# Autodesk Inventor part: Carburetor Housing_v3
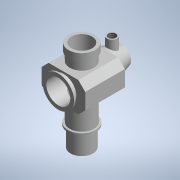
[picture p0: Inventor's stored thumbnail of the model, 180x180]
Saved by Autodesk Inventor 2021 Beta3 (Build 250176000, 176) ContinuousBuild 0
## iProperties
Created: 2012-08
Part Number: Carburetor Housing_v3
Material: Aluminum 6061
Document SubType Name: Modeling
Designer: John
Density: 2.71 g/cm^3
Mass: 9.58727 g
Surface Area: 43.1099 cm^2
Volume: 3.53774 cm^3
Appearance: Aluminum - Flat
Author: John
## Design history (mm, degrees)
sketch "Sketch1"
  geometry: L1 (-9.614, -8.788)-(9.614, -8.788); L2 (9.614, -8.788)-(9.614, 8.788); L3 (9.614, 8.788)-(-9.614, 8.788); L4 (-9.614, 8.788)-(-9.614, -8.788); L5 (-9.614, -8.788)-(9.614, 8.788); 2 further points
  constraints: 10 end point, 2 parallel, 1 coincident, 1 horizontal, 1 midpoint, 1 perpendicular
  dimensions: "d0" = 19.2278 distance of L2.end L3.end; "d2" = 17.5768 distance of L1.end L2.end
extrude "Extrusion1" new body sketch "Sketch1" stored distance "d3" = 13.1572; taper "d4" = 0 deg
sketch "Sketch2"
  geometry: L1 (9.614, 8.788)-(-9.614, 8.788) reference; L2 (-9.614, -8.788)-(9.614, -8.788) reference; L3 (0, 8.788)-(0, -8.788); C1 r 5.321 at (0, 0.686)
  constraints: 2 end point, 2 midpoint, 1 centre point, 1 point on line
  dimensions: "d5" = 10.6426 diameter of C1; "d9" = 8.1026 distance from line of L1 C1.centre
extrude "Extrusion2" join sketch "Sketch2" distance "d7" = 7.0612; taper "d8" = 0 deg
sketch "Sketch8"
  geometry: C1 r 5.321 at (0, 0) reference; C2 r 5.867 at (0, 0); 1 further point
  constraints: 1 centre point, 1 coincident
  dimensions: "d30" = 11.7348 diameter of C2
extrude "Extrusion6" join sketch "Sketch8" distance "d114" = 8.763; taper "d115" = 0 deg
sketch "Sketch3"
  geometry: C1 r 5.321 at (0, 0.686) reference; C2 r 5.321 at (0, 0.686)
  constraints: 1 centre point, 1 coincident
  dimensions: "d10" = 10.6426 diameter of C2
extrude "Extrusion3" join sketch "Sketch3" distance "d32" = 3.2512; taper "d33" = 0 deg
sketch "Sketch4"
  geometry: L1 (0, 0)-(19.228, -13.157); C1 r 5.715 at (9.614, -6.579)
  constraints: 2 end point, 1 centre point, 1 midpoint
  dimensions: "d13" = 11.43 diameter of C1
extrude "Extrusion4" join sketch "Sketch4" distance "d11" = 10.2616; taper "d12" = 0 deg
sketch "Sketch5"
  geometry: C1 r 5.715 at (0, 0) reference; C2 r 6.96 at (0, 0); 1 further point
  constraints: 1 centre point, 1 coincident
  dimensions: "d17" = 13.9192 diameter of C2
extrude "Extrusion5" join sketch "Sketch5" distance "d111" = 0.8382; taper "d112" = 0 deg
sketch "Sketch15"
  geometry: L1 (-16.967, 0)-(-16.967, 4.14); L2 (6.007, -6.579)-(6.007, -16.84) reference; L3 (-4.635, -16.84)-(-4.635, -6.579) reference; L4 (-4.635, -6.579)-(-8.788, -6.579) reference; L5 (-8.788, -6.579)-(-8.788, 6.579) reference; L6 (-8.788, 6.579)-(-4.635, 6.579) reference; L7 (-4.635, 6.579)-(-4.635, 10.389) reference; L8 (-4.635, 10.389)-(-5.182, 10.389) reference; L9 (-5.182, 10.389)-(-5.182, 13.64) reference; L10 (-5.182, 13.64)-(6.553, 13.64) reference; L11 (6.553, 13.64)-(6.553, 10.389) reference; L12 (6.553, 10.389)-(6.007, 10.389) reference; L13 (6.007, 10.389)-(6.007, 6.579) reference; L14 (6.007, 6.579)-(8.788, 6.579) reference; L15 (8.788, 6.579)-(8.788, 5.715) reference; L16 (8.788, 5.715)-(10.389, 5.715) reference; L17 (10.389, 5.715)-(10.389, 6.96) reference; L18 (10.389, 6.96)-(11.074, 6.96) reference; L19 (11.074, 6.96)-(11.074, -6.96) reference; L20 (11.074, -6.96)-(10.389, -6.96) reference; L21 (10.389, -6.96)-(10.389, -5.715) reference; L22 (10.389, -5.715)-(8.788, -5.715) reference; L23 (8.788, -5.715)-(8.788, -6.579) reference; L24 (8.788, -6.579)-(6.007, -6.579) reference; L25 (-8.788, 0)-(-16.967, 0); L26 (-16.967, 4.14)-(-8.788, 6.401); L27 (-8.788, 0)-(-8.788, 6.401); L28 (6.007, -16.84)-(6.845, -16.84) reference; L29 (6.845, -16.84)-(6.845, -17.678) reference; L30 (6.845, -17.678)-(5.639, -17.678) reference; L31 (5.639, -17.678)-(5.639, -26.441) reference; L32 (5.639, -26.441)-(-4.267, -26.441) reference; L33 (-4.267, -26.441)-(-4.267, -17.678) reference; L34 (-4.267, -17.678)-(-5.474, -17.678) reference; L35 (-5.474, -17.678)-(-5.474, -16.84) reference; L36 (-5.474, -16.84)-(-4.635, -16.84) reference; 1 further point
  constraints: 8 end point, 1 collinear, 1 midpoint, 1 parallel, 1 point on line
  dimensions: "d119" = 4.1402 distance of L1.start L1.end; "d136" = 8.1788 distance of L25.start L1.start; "d137" = 6.4008 distance from line of L25 L26.end
revolve "Revolution1" sketch "Sketch15" stored, may be unused: angle "d120" = 90 deg
hole "Hole2" diameter "d68" = 9.0678; stored, may be unused: countersink angle "d72" = 82 deg, drill point angle "d74" = 0 deg; dims "d69" = 19.05, "d70" = 9.525, "d71" = 6.35, "d73" = 16.8402, "d105" = 25.4, "d106" = 25.4
hole "Hole4" diameter "d153" = 3.302; stored, may be unused: countersink angle "d157" = 82 deg, drill point angle "d159" = 118 deg; dims "d151" = 25.4, "d152" = 25.4, "d154" = 19.05, "d155" = 9.525, "d156" = 6.35, "d158" = 25.4
chamfer "Chamfer1" distance "d101" = 3.175; stored, may be unused: second distance "d102" = 3.175, angle "d103" = 45 deg
body "Solid1"
extrude "Extrusion7" join sketch "Sketch4" distance "d15" = 2.286; taper "d16" = 0 deg
extrude "Extrusion8" join sketch "Sketch5" distance "d19" = 0.6858; taper "d20" = 0 deg
sketch "Sketch17"
  geometry: L1 (-9.614, -8.788)-(-9.614, 8.788) reference; L2 (-9.614, 8.788)-(-5.715, 8.788) reference; L3 (-5.715, 8.788)-(-5.715, 10.389) reference; L4 (-5.715, 10.389)-(-6.96, 10.389) reference; L5 (-6.96, 10.389)-(-6.96, 11.074) reference; L6 (-6.96, 11.074)-(6.96, 11.074) reference; L7 (6.96, 11.074)-(6.96, 10.389) reference; L8 (6.96, 10.389)-(5.715, 10.389) reference; L9 (5.715, 10.389)-(5.715, 8.788) reference; L10 (5.715, 8.788)-(9.614, 8.788) reference; L11 (9.614, 8.788)-(9.614, -8.788) reference; L12 (9.614, -8.788)-(6.401, -8.788) reference; L13 (6.401, -8.788)-(4.14, -16.967) reference; L14 (4.14, -16.967)-(-4.14, -16.967) reference; L15 (-4.14, -16.967)-(-6.401, -8.788) reference; L16 (-6.401, -8.788)-(-9.614, -8.788) reference; L17 (0, -16.967)-(0, -12.7); C1 r 2.223 at (0, -12.7); 1 further point
  constraints: 2 end point, 1 centre point, 1 coincident, 1 midpoint, 1 perpendicular
  dimensions: "d138" = 4.2672 distance of L17.start L17.end; "d139" = 4.445 diameter of C1
extrude "Extrusion9" join sketch "Sketch17" distance "d140" = 9.525; taper "d141" = 0 deg
hole "Hole1" diameter "d45" = 10.5918; stored, may be unused: countersink angle "d49" = 82 deg, drill point angle "d51" = 0 deg; dims "d43" = 25.4, "d44" = 25.4, "d46" = 19.05, "d47" = 9.525, "d48" = 6.35, "d50" = 16.8402
hole "Hole3" diameter "d144" = 6.8072; stored, may be unused: countersink angle "d148" = 82 deg, drill point angle "d150" = 118 deg; dims "d145" = 19.05, "d146" = 9.525, "d147" = 6.35, "d149" = 25.4, "d160" = 25.4, "d161" = 25.4
sketch "Sketch12"
  geometry: C1 r 5.321 at (0, 0) reference; C2 r 6.159 at (0, 0); 1 further point
  constraints: 1 centre point, 1 coincident
  dimensions: "d109" = 12.319 diameter of C2
sketch "Sketch13"
  geometry: C1 r 6.159 at (0, 0) reference; C2 r 4.953 at (0, 0)
  constraints: 1 centre point, 1 coincident
  dimensions: "d113" = 9.906 diameter of C2
node "Project Cut Edges3"
node "Project Cut Edges4"
